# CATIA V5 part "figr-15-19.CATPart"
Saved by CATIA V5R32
Part number: Part1
Bounding box of the stored display mesh (mm): x -46.56 to 46.56, y -36.965 to 25.965, z 0 to 40
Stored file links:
  D:\PROJECTS\Project 2022\CATIA V5 6R 2022\Resources\Part Files\c15_catia_v5_6r2022_prt\figr-15-19.CATPart
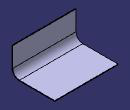
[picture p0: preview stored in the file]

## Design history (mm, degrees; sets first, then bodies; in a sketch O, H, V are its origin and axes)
SheetMetalParameters1: Thickness 1, BendRadius 1, KFactor 0.325257 {= log(min(100,max(20*SheetMetalParameters1.BendRadius,SheetMetalParameters1.Thickness)/SheetMetalParameters1.Thickness))/log(100)/2}, ReliefRadialLength 1, ReliefAxialLength 2, MinimumBendRadius 0
Body1 (main body)
  Sketch1 on xy-plane, origin (0, 0, 0), H (1, 0, 0), V (0, 1, 0)
    line L1 (-46.5596, 25.9646) -> (46.5596, 25.9646)
    line L2 (46.5596, 25.9646) -> (46.5596, -25.9646)
    line L3 (46.5596, -25.9646) -> (-46.5596, -25.9646)
    line L4 (-46.5596, -25.9646) -> (-46.5596, 25.9646)
    horizontal: L1 H, L3 H
    vertical: L2 V, L4 V
    symmetry: L1 L3 H, L4 L2 V
  Wall1: Thickness 1, Profile Sketch1
  d_NewWallOnEdge1: NewWallOnEdge_Edge edge [face of Wall1 | face of Wall1], NewWallOnEdge_Length 40, NewWallOnEdge_HeightLimitOffset 0, NewWallOnEdge_WidthOffset1 0, NewWallOnEdge_WidthOffset2 0, NewWallOnEdge_Angle 90, NewWallOnEdge_BendRadiusValue 10 {= d_NewWallOnEdge1.Clearance}, NewWallOnEdge_BendTable SheetMetalParameters1, KFacteur 0.5 {= log(min(100,max(20*d_NewWallOnEdge1.Radius,SheetMetalParameters1.Thickness)/SheetMetalParameters1.Thickness))/log(100)/2}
